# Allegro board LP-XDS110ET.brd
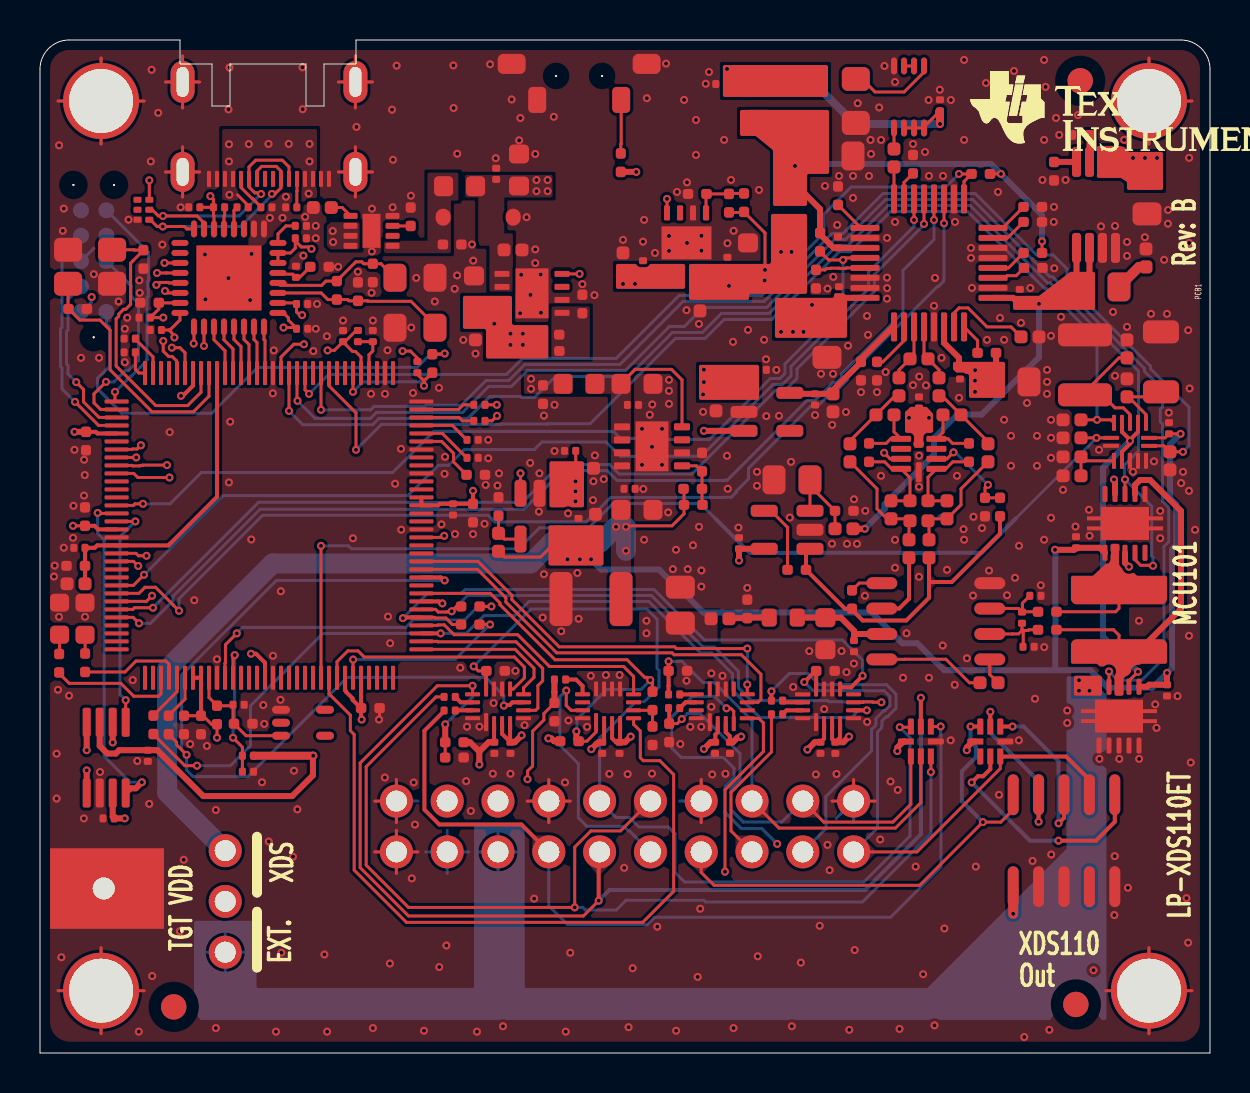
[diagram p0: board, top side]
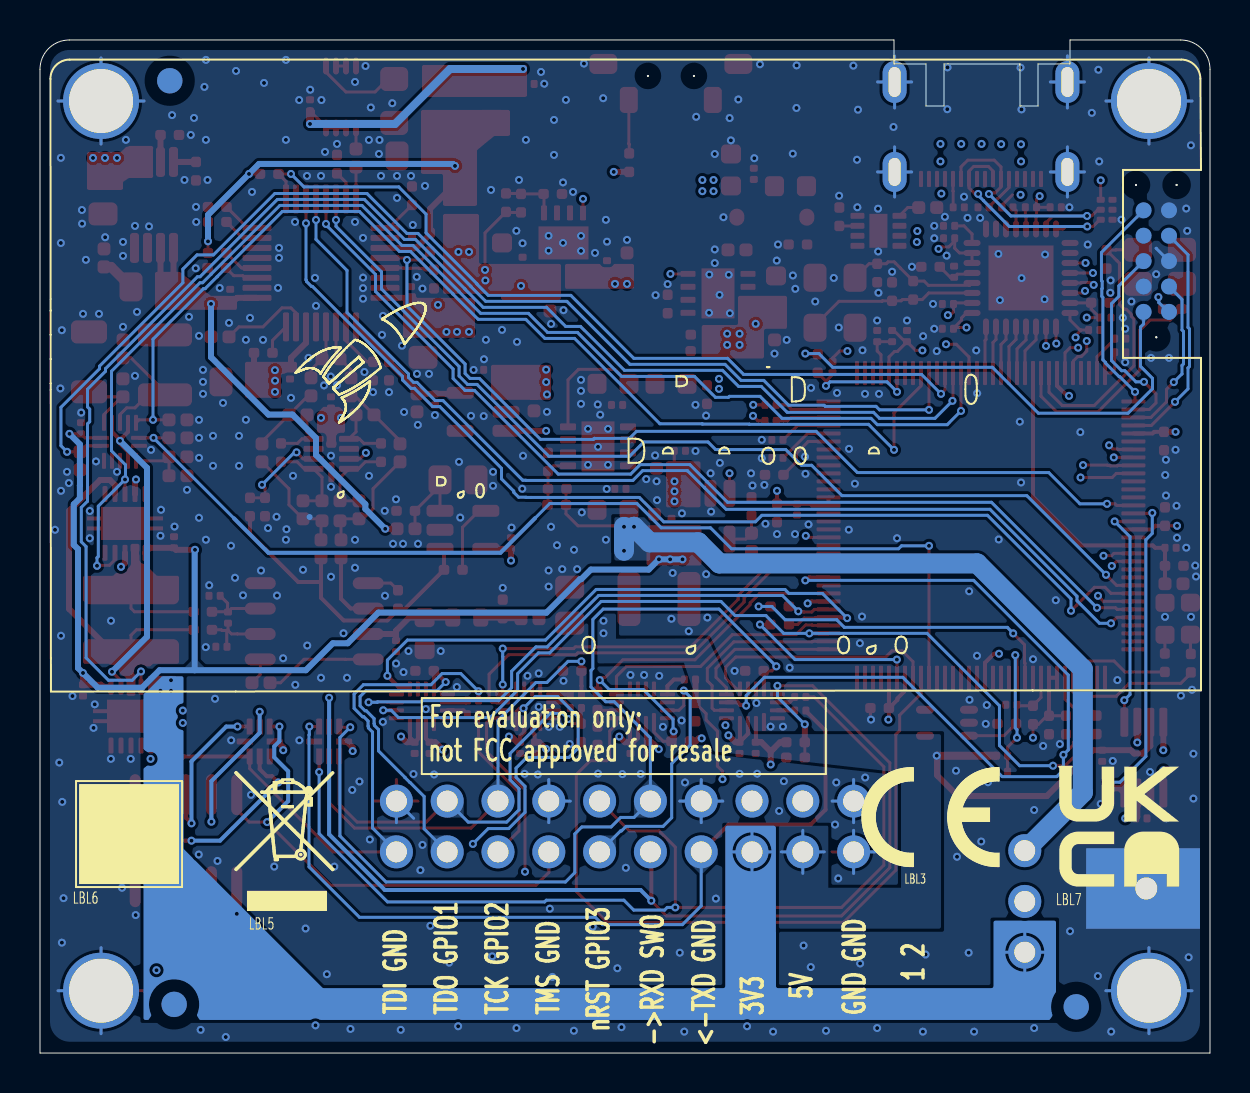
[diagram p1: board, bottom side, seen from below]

Outline 58.5 x 50.67 mm; copper layers: TOP, L2, L3, BOTTOM. Coordinates in mm from the lower left corner of the outline.
Outline path: 0,49.21 0,0 58.5,0 58.5,49.21 arc(58.07,50.24) 57.04,50.67 15.8,50.67 15.8,49.47 14.2,49.47 14.2,47.37 13.3,47.37 13.3,49.47 9.5,49.47 9.5,47.37 8.6,47.37 8.6,49.47 7,49.47 7,50.67 1.46,50.67 arc(0.43,50.24) 0,49.21

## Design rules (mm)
constraint set DEFAULT: min track width 0.15
nets with their own width: min track width 0.15; nets GND

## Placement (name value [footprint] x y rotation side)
C1  12pF  [CAPC1005X60B2N]  5.17 40.16 270 top
C2  10nF  [CAPC1005X60B2N]  16.05 17.25 0 top
C3  10nF  [CAPC1005X60B2N]  2.3 31.07 270 top
C4  10nF  [CAPC1005X60B2N]  2.25 26.37 90 top
C6  100nF  [CAPC0603X35B2N]  6.07 36.16 180 top
C7  10nF  [CAPC1005X60B2N]  7.2 16.87 270 top
C8  100nF  [CAPC0603X35B2N]  9.65 17.42 0 top
C9  12pF  [CAPC1005X60B2N]  1.42 37.22 0 top
C10  100nF  [CAPC0603X35B2N]  5.39 15.15 270 top
C11  100nF  [CAPC0603X35B2N]  3.71 11.74 180 top
C38  100nF  [CAPC0603X35B2N]  20.65 27.47 270 top
C39  100nF  [CAPC0603X35B2N]  15.15 35.58 90 top
C40  1uF  [CAPC1005X60B2N]  21.65 27.47 270 top
C42  1uF  [CAPC1005X60B2N]  8.05 16.87 270 top
C43  100nF  [CAPC0603X35B2N]  2.25 25.27 180 top
C44  1uF  [CAPC1005X60B2N]  2.25 24.37 180 top
C45  2.2uF  [CAPC1005X60A2N]  2.25 23.47 180 top
C46  100nF  [CAPC0603X35B2N]  16.64 35.58 90 top
C47  15pF  [CAPC1005X60B2N]  25.04 35.11 0 top
C48  2.2uF  [CAPC1005X60A2N]  23.2 40.17 0 top
C49  2.2uF  [CAPC1005X60A2N]  22.67 35.67 180 top
C50  10nF  [CAPC1005X60B2N]  9.7 16.47 0 top
C70  100nF  [CAPC0603X35B2N]  22.72 15.55 270 top
C71  100nF  [CAPC0603X35B2N]  23.52 15.55 270 top
C72  100nF  [CAPC0603X35B2N]  28.11 15.55 270 top
C73  100nF  [CAPC0603X35B2N]  28.98 15.55 270 top
C74  100nF  [CAPC0603X35B2N]  39.02 15.55 270 top
C75  100nF  [CAPC0603X35B2N]  39.77 15.55 270 top
C78  100nF  [CAPC0603X35B2N]  12.83 36.23 0 top
C79  100nF  [CAPC0603X35B2N]  7.99 42.3 180 top
C80  100nF  [CAPC0603X35B2N]  12.76 40.75 0 top
C83  100nF  [CAPC0603X35B2N]  5.51 36.78 180 top
C84  100nF  [CAPC0603X35B2N]  12.83 37.47 0 top
C85  4.7uF  [CAPC1005X60B2N]  5.94 37.53 180 top
C86  4.7uF  [CAPC1005X60B2N]  13.51 39.33 0 top
C87  100nF  [CAPC0603X35B2N]  12.8 38.8 90 top
C88  12pF  [CAPC1005X60B2N]  15.9 38.55 270 top
C89  12pF  [CAPC1005X60B2N]  16.64 39.48 270 top
C108  33nF  [CAPC1005X60A2N]  14.56 42.29 180 top
C109  10nF  [CAPC1005X60B2N]  20.15 40.44 0 top
C110  100nF  [CAPC0603X35B2N]  22.81 43.7 90 top
C111  3.3uF  [CAPC1608X100A2N]  23.95 43.37 90 top
C113  22uF  [CAPC1608X100A2N]  21.7 37.27 90 top
C114  100nF  [CAPC0603X35B2N]  56.35 18.42 270 top
C115  100nF  [CAPC0603X35B2N]  34.35 48.47 180 top
C116  100nF  [CAPC0603X35B2N]  39.9 40.27 90 top
C117  10uF  [CAPC2012X150A2N]  38.85 44.87 0 top
C118  100nF  [CAPC0603X35B2N]  45 47.12 90 top
C119  100nF  [CAPC0603X35B2N]  46 34.27 270 top
C120  100nF  [CAPC0603X35B2N]  39.95 37.77 90 top
C121  10uF  [CAPC2012X150A2N]  39.35 36.6 270 top
C122  10uF  [CAPC2012X150A2N]  47.65 33.57 0 top
C123  270pF  [CAPC1005X60B2N]  41.45 29.57 90 top
C124  100nF  [CAPC0603X35B2N]  50.05 22.87 180 top
C125  100nF  [CAPC0603X35B2N]  40.7 20.07 90 top
C126  100nF  [CAPC0603X35B2N]  43.95 32.82 270 top
C127  100nF  [CAPC0603X35B2N]  48.99 37.64 90 top
C128  1uF  [CAPC1005X60B2N]  41.05 34.57 270 top
C129  470pF  [CAPC1005X60A2N]  43.5 26.62 0 top
C130  1nF  [CAPC1005X60A2N]  43.5 27.62 0 top
C131  22nF  [CAPC1005X60A2N]  43.5 34.72 0 top
C132  100nF  [CAPC0603X35B2N]  49.1 22.06 270 top
C133  1uF  [CAPC1005X60B2N]  47.25 27.77 270 top
C134  100nF  [CAPC0603X35B2N]  49.15 20.32 0 top
C135  270pF  [CAPC1005X60B2N]  46.45 29.57 90 top
C136  1uF  [CAPC1005X60B2N]  41.85 34.57 270 top
C137  1uF  [CAPC1005X60B2N]  49.2 39.27 0 top
C138  1uF  [CAPC1005X60B2N]  39.9 42.42 90 top
C139  100nF  [CAPC0603X35B2N]  51.8 25.27 90 top
C140  100nF  [CAPC0603X35B2N]  56.45 30.97 90 top
C141  100nF  [CAPC0603X35B2N]  34.95 25.22 90 top
C142  10uF  [CAPC2012X150A2N]  55.35 43.77 270 top
C143  2.2uF  [CAPC1005X60A2N]  54.35 32.82 90 top
C144  2.2uF  [CAPC1005X60A2N]  54.35 34.77 90 top
C145  1uF  [CAPC1005X60B2N]  50.7 44.57 270 top
C146  47uF  [CAPC2012X150A2N]  52.15 38.32 0 top
C147  10uF  [CAPC2012X150A2N]  38.5 28.67 180 top
C149  2.2uF  [CAPC1005X60A2N]  52.05 29.82 180 top
C151  2.2uF  [CAPC1005X60A2N]  29.15 39.12 90 top
C152  100nF  [CAPC0603X35B2N]  30.15 39.07 90 top
C153  15pF  [CAPC1005X60B2N]  35.2 42.07 90 top
C154  100nF  [CAPC0603X35B2N]  34.37 39.24 90 top
C155  2.2uF  [CAPC1005X60A2N]  33 38.02 270 top
C156  22uF  [CAPC1608X100A2N]  35.4 38.92 90 top
C157  2.2uF  [CAPC1005X60A2N]  33.8 33.02 270 top
C158  100nF  [CAPC0603X35B2N]  38.75 32.97 270 top
C159  2.2uF  [CAPC1005X60A2N]  39.65 32.97 270 top
C160  2.2uF  [CAPC1005X60A2N]  26.77 29.25 0 top
C161  100nF  [CAPC0603X35B2N]  26.79 30.12 180 top
C162  100nF  [CAPC0603X35B2N]  26.92 26.18 90 top
C163  2.2uF  [CAPC1005X60A2N]  27.77 26.05 90 top
C164  100nF  [CAPC0603X35B2N]  35.76 34.17 0 top
C165  22uF  [CAPC1608X100A2N]  39.27 21.77 270 top
C166  10nF  [CAPC1005X60B2N]  35.36 21.75 90 top
C168  10uF  [CAPC2012X150A2N]  32.02 21.5 90 top
C171  22uF  [CAPC1608X100A2N]  29.05 33.47 0 top
C172  15pF  [CAPC1005X60B2N]  32.2 27.42 0 top
C174  22uF  [CAPC1608X100A2N]  29.05 27.17 0 top
C175  100nF  [CAPC0603X35B2N]  29.37 32.42 0 top
C484  10nF  [CAPC1005X60B2N]  25.15 33.39 270 top
C485  100nF  [CAPC0603X35B2N]  29.2 28.22 0 top
C486  220uF  [CAPC3225X280A2N]  29.05 22.71 180 top
C487  100nF  [CAPC0603X35B2N]  34.5 15.55 270 top
C488  100nF  [CAPC0603X35B2N]  33.75 15.55 270 top
CR4  LS_Q976-NR-1  [LEDC1608X80B2N]  0.98 22.52 270 top
CR5  LG_Q396-PS-35  [LEDC1608X40N]  2.25 22.52 270 top
CR6  TPD4E004DRY  [SON50P100X145X60-6N]  4.88 42.68 270 top
CR7  TPD6E004RSER  [QFN50P150X150X60-8N]  47.02 14.83 0 top
CR15  MBR130T1  [SOD3716X135N]  20.16 41.81 0 top
CR16  TPD6E004RSER  [QFN50P150X150X60-8N]  43.54 14.83 0 top
FIDU1  FIDU_1.27mm  [FID127X142]  52.01 48.63 0 top
FIDU2  FIDU_1.27mm  [FID127X142]  6.69 2.31 0 top
FIDU3  FIDU_1.27mm  [FID127X142]  51.79 2.43 0 top
FIDU4  FIDU_1.27mm  [FID127X142]  52.01 48.63 180 bottom
FIDU5  FIDU_1.27mm  [FID127X142]  6.69 2.31 180 bottom
FIDU6  FIDU_1.27mm  [FID127X142]  51.79 2.43 180 bottom
FL2  BLM18HE152SN1  [FIL_BLM18HE152SN1DN#2]  21.78 43.36 180 top
FL4  BLM18HE152SN1  [FIL_BLM18HE152SN1DN]  37.86 21.78 180 top
FL5  BLM18HE152SN1  [FIL_BLM18HE152SN1DN#2]  27.75 33.47 180 top
J1  U20405-2  [MUP_U204052_A2N]  14.45 43.72 90 top
L332  BLM21PG221SN1  [FILC2012X110A2N]  35.92 46.6 90 top
L333  BLM21PG221SN1  [FILC2012X110A2N]  37.5 41.32 90 top
L334  BLM21PG221SN1  [FILC2012X110A2N]  37.5 37.02 90 top
LBL2  TI_LOGO  [TI_LOGO_1]  47.5 49.12 0 top
LBL3  CE_label  [CE_MARKING]  14.81 9.3 180 bottom
LBL4  -  [LABEL_FOR_EVALUATION_ONLY]  39.26 14.1 180 bottom
LBL5  TRASH_7mm  [TRASH_7MM]  48.15 7.11 180 bottom
LBL6  ESD_LABEL_5x5mm  [ESD_LABEL_5X5]  56.55 8.45 180 bottom
LBL7  LABEL_UKCA_6x6mm  [LABEL_UKCA_6MM]  7.54 8.32 180 bottom
M1  SNT-100-BK-G  [SAMTEC_SNT100BKG]  7.99 11.42 270 top
M15  DCB-10  [MECH_DCB10_A2B]  3.05 47.62 180 bottom
M16  DCB-10  [MECH_DCB10_A2B]  55.45 47.62 180 bottom
M17  DCB-10  [MECH_DCB10_A2B]  3.05 3.12 180 bottom
M18  DCB-10  [MECH_DCB10_A2B]  55.45 3.12 180 bottom
MH1  HOLE_3.2mm_PTH  [MTG320_380]  3.05 3.12 0 top
MH2  HOLE_3.2mm_PTH  [MTG320_380]  55.45 3.12 0 top
MH3  HOLE_3.2mm_PTH  [MTG320_380]  3.05 47.62 0 top
MH4  HOLE_3.2mm_PTH  [MTG320_380]  55.45 47.62 0 top
MH5  HOLE_1.1mm_PTH  [MTG110_170]  3.19 8.23 0 top
NOREF  -  []  0.85 -97.91 0 top
NOREF#2  -  []  -45.65 -121.98 0 top
NOREF#3  -  []  51.48 20.39 180 bottom
P7  FTSH-105-01-F-DV-K  [SAMTEC_FTSH-105-01-F-DV-K-10L]  48.66 8.32 0 top
P8  TC2050-IDC-NL  [TAGCONNECT_TC2050IDCNL_A2N]  2.05 37.07 90 bottom
P9  BB02-HC031-KB1-603000  [GRADCONN_BB02HC031KB1603000_A2B]  9.26 10.12 270 top
P10  CNT-B254-210-GD-910/3.2  [CNT_CNTB254210GD91032_A2B]  17.82 10.06 0 top
PCB1  MCU101  [TI_MCUXX]  57.45 37.77 90 top
R8  51  [RESC0603X35B2N]  25.72 18.68 0 top
R9  51  [RESC0603X35B2N]  36.57 17.63 0 top
R10  100k  [RESC1005X40B2N]  32.35 19.11 180 top
R11  100k  [RESC1005X40B2N]  31.46 15.55 90 top
R12  51  [RESC0603X35B2N]  31.43 17.25 0 top
R13  51  [RESC0603X35B2N]  31.43 17.94 0 top
R14  51  [RESC0603X35B2N]  20.2 17.13 0 top
R15  51  [RESC0603X35B2N]  20.2 17.81 0 top
R16  51  [RESC0603X35B2N]  36.57 16.94 0 top
R17  10k  [RESC0603X35B2N]  18.87 34.03 90 top
R18  4.7k  [RESC1005X40B2N]  8.85 17.37 270 top
R20  100  [RESC1005X40B2N]  19.62 34.03 90 top
R23  180  [RESC1005X40B2N]  0.96 19.96 270 top
R25  220  [RESC1005X40B2N]  2.26 19.98 270 top
R27  1k  [RESC0603X35B2N]  22.25 31.62 180 top
R28  4.87k  [RESC1005X40B2N]  22.25 28.92 180 top
R29  1k  [RESC0603X35B2N]  21.35 30.67 0 top
R30  1k  [RESC0603X35B2N]  21.35 29.77 0 top
R31  51  [RESC0603X35B2N]  15.9 35.58 90 top
R33  51k  [RESC1005X40B2N]  25.96 35.93 180 top
R34  30k  [RESC1005X40B2N]  27.12 37.93 270 top
R39  1k  [RESC0603X35B2N]  22.25 32.42 180 top
R57  100  [RESC1005X40B2N]  29.04 44.07 90 top
R58  3.3k  [RESC1005X40B2N]  26.93 15.6 180 top
R61  100k  [RESC1005X40B2N]  20.26 15.54 0 top
R62  100k  [RESC1005X40B2N]  23.24 19.11 180 top
R63  100k  [RESC1005X40B2N]  39.73 19.11 180 top
R65  100k  [RESC1005X40B2N]  25.72 16.59 90 top
R82  10k  [RESC0603X35B2N]  9.85 42.3 0 top
R83  10k  [RESC0603X35B2N]  8.67 42.3 0 top
R84  12k  [RESC0603X35B2N]  13.32 41.37 180 top
R87  1Meg  [RESC1005X40B2N]  14.84 37.69 90 top
R90  1k  [RESC0603X35B2N]  4.21 35.73 0 top
R91  1k  [RESC0603X35B2N]  4.21 35.05 0 top
R92  10k  [RESC0603X35B2N]  10.12 14.87 0 top
R93  20k  [RESC0603X35B2N]  10.12 14.07 0 top
R94  22  [RESC1005X40A2N]  42.7 44.32 90 top
R95  1.2k  [RESC1005X40A2N]  40.5 30.47 270 top
R96  100k  [RESC1005X40B2N]  47.5 43.97 180 top
R97  100k  [RESC1005X40B2N]  38.8 39.17 270 top
R98  100k  [RESC1005X40B2N]  47.8 35.02 180 top
R99  0  [RESC1005X40B2N]  49.9 22.07 0 top
R100  0  [RESC1005X40B2N]  40.6 22.22 90 top
R101  1.2k  [RESC1005X40A2N]  43.45 25.67 270 top
R102  330  [RESC1005X40A2N]  42.55 27.62 270 top
R103  4.99  [RESC1005X40A2N]  41.8 31.92 0 top
R104  10  [RESC1005X40A2N]  42.95 33.77 270 top
R105  100k  [RESC1005X40B2N]  43.65 44.92 270 top
R107  1  [RESC3246X70A2N]  53.95 20.12 90 top
R108  0  [RESC1005X40B2N]  49.9 21.17 0 top
R109  1.2k  [RESC1005X40A2N]  44.45 25.67 270 top
R110  330  [RESC1005X40A2N]  45.35 27.62 270 top
R111  0  [RESC1005X40B2N]  48 27.77 270 top
R112  4.99  [RESC1005X40A2N]  46.05 31.92 180 top
R113  10  [RESC1005X40A2N]  44.95 33.77 270 top
R114  100k  [RESC1005X40B2N]  39 41.02 270 top
R116  60.4k  [RESC1005X40A2N]  49.95 35.82 180 top
R117  100k  [RESC1005X40B2N]  50.1 42.32 180 top
R118  100k  [RESC1005X40B2N]  50.1 41.57 180 top
R119  100k  [RESC1005X40B2N]  50.1 40.02 180 top
R120  1.2k  [RESC1005X40A2N]  47.4 30.47 270 top
R121  22k  [RESC1005X40A2N]  40.65 26.22 180 top
R122  0.22  [RESC1005X50A2N]  55.3 40.22 270 top
R123  82  [RESC3216X75A2N]  56.05 36.07 270 top
R125  36.5  [RESC3225X75A2N]  52.25 35.92 270 top
R126  4.7k  [RESC1005X40B2N]  39.75 27.12 0 top
R127  47k  [RESC1005X40A2N]  52.05 30.77 180 top
R128  47k  [RESC1005X40A2N]  52.05 31.67 180 top
R129  47k  [RESC1005X40A2N]  56.5 30.07 270 top
R130  2.2k  [RESC1005X40A2N]  52.05 28.87 180 top
R131  0  [RESC1005X40B2N]  38.3 24.17 180 top
R132  51k  [RESC1005X40B2N]  34.45 42.97 270 top
R133  30k  [RESC1005X40B2N]  32.4 42.97 0 top
R134  60.4k  [RESC1005X40A2N]  22.92 26 270 top
R135  30k  [RESC1005X40B2N]  22.92 27.8 270 top
R136  100k  [RESC1005X40B2N]  51.55 45.92 0 top
R137  2.61k  [RESC1005X40A2N]  47 18.52 0 top
R151  51k  [RESC1005X40B2N]  33.1 28.22 180 top
R152  30k  [RESC1005X40B2N]  33.1 30.02 270 top
R353  4.7k  [RESC1005X40B2N]  18.53 42.29 270 top
R354  10  [RESC1005X40A2N]  34.45 21.72 180 top
R357  5.1k  [RESC0603X35B2N]  12.28 42.3 0 top
R358  5.1k  [RESC0603X35B2N]  11.6 42.3 180 top
R359  100k  [RESC1005X40B2N]  21.18 14.78 180 top
R360  0  [RESC1005X40B2N]  6.44 16.87 270 top
R361  0  [RESC1005X40B2N]  21.98 22.34 180 top
R362  0  [RESC1005X40B2N]  21.97 21.43 180 top
R363  0  [RESC1005X40B2N]  30.63 18.07 270 top
R364  0  [RESC1005X40B2N]  30.63 16.33 270 top
R365  0  [RESC1005X40B2N]  5.67 16.88 270 top
SW3  1188E-1K2  [SW_1188E1K2V_A2N]  30.33 49.47 180 top
U5  MSP432E401YTPDT  [QFP40P1600X1600X120-128A2N]  5.25 18.77 0 top
U6  LM4040B25IDCK  [SOT65P210X110-5N]  12.05 17.17 270 top
U7  TPS79601DR  [SON65P300X300X100-9AN]  23.1 38.97 270 top
U8  SN74AVC4T245RSV  [QFNFC40P180X260X55-16A2N]  22.3 16.55 0 top
U9  SN74AVC4T245RSV  [QFNFC40P180X260X55-16A2N]  38.8 16.55 0 top
U10  SN74AVC4T245RSV  [QFNFC40P180X260X55-16A2N]  27.8 16.55 0 top
U15  USB3300-EZK  [QFNWB50P500X500X100-33N]  11.2 41.22 180 top
U33  TS3A24159DRC  [SON50P300X300X100-11A2N]  53.25 25.02 0 top
U34  SN74LVC2G74DCU  [SOP50P310X90-8N]  44.2 49.37 180 top
U35  ADS127L01IPBS  [QFP50P700X700X120-32A2N]  42.7 36.32 0 top
U36  INA118UB  [SOIC127P600X175-8N]  47.49 19.69 90 top
U37  THS4551IRUN  [QFNFCP50P200X200X80-10A2N]  43.05 30.72 270 top
U38  TS3A24159DRC  [SON50P300X300X100-11A2N]  54.95 18.32 180 top
U39  TS3A4751RUCR  [QFNFC40P200X200X40-14A2N]  55.3 31.52 180 top
U40  REF6025IDGK  [SOP65P490X110-8A2N]  53.77 44.57 180 top
U41  OPA320AIDBV  [SOT95P280X145-5A2N]  38.5 25.22 90 top
U42  TPS79601DR  [SON65P300X300X100-9AN]  31.35 39.02 0 top
U43  LP5907MFX-1.8  [SOT95P280X145-5A2N]  35.2 33.02 270 top
U44  TPS73101DBV  [SOT95P280X145-5A2N]  25.92 28 180 top
U46  TPS79601DR  [SON65P300X300X100-9AN]  29.1 31.32 270 top
U47  TPS259530DSG  [SON50P200X200X80-9A2N]  15.53 41.87 270 top
U49  SN74AVC4T245RSV  [QFNFC40P180X260X55-16A2N]  33.49 16.55 0 top
U50  TCA9406DCT  [SOP65P400X130-8A2N]  2.33 13 0 top
Y3  16MHz  [OSCCC250X320X100-4BN]  1.4 38.48 0 top
Y4  24MHz  [OSCCC250X320X70-4AN]  17.75 38.78 270 top
Y5  16.384MHz  [OSCSC254P320X500X130-4A2N]  38.25 46.52 0 top

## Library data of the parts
C1-C4 C7 C9 C40 C42 C44 C47 C50 C85 C86 C88 C89 C109 C123 C128 C133 C135-C138 C145 C153 C166 C172 C484 = CAPACITOR: User Part Number: #PN
C6 C8 C10 C11 C38 C39 C43 C46 C70-C75 C78-C80 C83 C84 C87 C110 C114-C116 C118-C120 C124-C127 C132 C134 C139-C141 C152 C154 C158 C161 C162 C164 C175 C485 C487 C488 = CAPACITOR: User Part Number: #PN; alternate symbols: (CAPC0603X35B2L,CAPC0603X35B2M)
C45 C48 C49 C108 C129-C131 C143 C144 C149 C151 C155 C157 C159 C160 C163 = CAPACITOR: User Part Number: #PN; alternate symbols: (CAPC1005X60A2L,CAPC1005X60A2M)
C111 C113 C156 C165 C171 C174 = CAPACITOR: User Part Number: #PN; alternate symbols: (CAPC1608X100A2L,CAPC1608X100A2M)
C117 C121 C122 C142 C146 C147 C168 = CAPACITOR: User Part Number: #PN; alternate symbols: (CAPC2012X150A2L,CAPC2012X150A2M)
C486 = CAPACITOR: User Part Number: #PN; alternate symbols: (CAPC3225X280A2L,CAPC3225X280A2M)
CR4 = LED: User Part Number: #PN; alternate symbols: (LEDC1608X80B2L,LEDC1608X80B2M)
CR5 = LED: alternate symbols: (LEDC1608X40L,LEDC1608X40M)
CR6 = DIODE_TPD4E004_SON6: User Part Number: #PN; alternate symbols: (SON50P100X145X65-6L,SON50P100X145X65-6M)
CR7 CR16 = DIODE_TVS_TPD6E004_QFN8_V1: User Part Number: #PN; alternate symbols: (QFN50P150X150X60-8L,QFN50P150X150X60-8M)
CR15 = DIODE_SCHOTTKY: alternate symbols: (SOD3716X135L,SOD3716X135M,SOD3716X135BN)
FIDU1-FIDU6 = FIDMARK
FL2 FL4 FL5 = FILTER_2PIN: alternate symbols: (FIL_BLM18HE152SN1DL,FIL_BLM18HE152SN1DM)
J1 = CONN_USB_TYPE-C_16PINS: User Part Number: #PN; alternate symbols: (MUP_U204052_A2L,MUP_U204052_A2M)
L332-L334 = INDUCTOR: User Part Number: #PN; alternate symbols: (FILC2012X110A2L,FILC2012X110A2M)
LBL2 = TI_LOGO_V1
LBL3 = CE_LABEL_V1
LBL4 = LABEL_FOR_EVALUATOIN_ONLY: User Part Number: #PN
LBL5 = TRASH_V2: User Part Number: #PN
LBL6 = ESD_LABEL: User Part Number: #PN
LBL7 = LABEL_UKCA: User Part Number: #PN
M1 = MECH_SHUNT_JUMPER_V1: User Part Number: #PN
M15-M18 = MECH_SPACERS_SUPPORT_V1: User Part Number: #PN
MH1-MH5 = HOLE_PTH
P7 = CONN_HEADER_2X5: alternate symbols: (SAMTEC_FTSH10501FDVK_A2L,SAMTEC_FTSH10501FDVK_A2M)
P8 = CONN_IDC_TC2050-IDC-NL: User Part Number: #PN; alternate symbols: (TAGCONNECT_TC2050IDCNL_A2L,TAGCONNECT_TC2050IDCNL_A2M)
P9 = CONN_HEADER_3_P_S: User Part Number: #PN; alternate symbols: (GRADCONN_BB02HC031KB1603000_A2C,GRADCONN_BB02HC031KB1603000_A2A)
P10 = CONN_HEADER_2X10_P_V3: User Part Number: #PN; alternate symbols: (CNT_CNTB254210GD91032_A2A,CNT_CNTB254210GD91032_A2C)
PCB1 = PCB_V2: User Part Number: #PN
R8 R9 R12-R17 R27 R29-R31 R39 R82-R84 R90-R93 R357 R358 = RESISTOR: User Part Number: #PN; alternate symbols: (RESC0603X35B2L,RESC0603X35B2M)
R10 R11 R18 R20 R23 R25 R28 R33 R34 R57 R58 R61-R63 R65 R87 R96-R100 R105 R108 R111 R114 R117-R119 R126 R131-R133 R135 R136 R151 R152 R353 R359-R365 = RESISTOR: User Part Number: #PN
R94 R95 R101-R104 R109 R110 R112 R113 R116 R120 R121 R127-R130 R134 R137 R354 = RESISTOR: User Part Number: #PN; alternate symbols: (RESC1005X40A2L,RESC1005X40A2M)
R107 = RESISTOR: User Part Number: #PN; alternate symbols: (RESC3246X70A2L,RESC3246X70A2M)
R122 = RESISTOR: User Part Number: #PN; alternate symbols: (RESC1005X50A2L,RESC1005X50A2M)
R123 = RESISTOR: User Part Number: #PN; alternate symbols: (RESC3216X75A2L,RESC3216X75A2M)
R125 = RESISTOR: User Part Number: #PN; alternate symbols: (RESC3225X75A2L,RESC3225X75A2M)
SW3 = SWITCH_TACT_V2: alternate symbols: (SW_1188E1K2V_A2L,SW_1188E1K2V_A2M)
U5 = IC_PROC_MSP432E401Y_TQFP128: User Part Number: #PN; alternate symbols: (QFP40P1600X1600X120-128A2L,QFP40P1600X1600X120-128A2M)
U6 = IC_REF_LM4040_SC70-5: alternate symbols: (SOT65P210X110-5L,SOT65P210X110-5M)
U7 U42 U46 = IC_PM_TPS79601_SON8: alternate symbols: (SON65P300X300X100-9AL,SON65P300X300X100-9AM)
U8-U10 U49 = IC_XCVR_SN74AVC4T245_UQFN16_2: User Part Number: #PN; alternate symbols: (QFNFC40P180X260X55-16A2L,QFNFC40P180X260X55-16A2M)
U15 = IC_PROC_USB3300_QFN32: alternate symbols: (QFNWB50P500X500X100-33L,QFNWB50P500X500X100-33M,QFNWB50P500X500X100-33DL,QFNWB50P500X500X100-33DM)
U33 U38 = IC_SWITCH_TS3A24159_SON10: User Part Number: #PN; alternate symbols: (SON50P300X300X100-11A2L,SON50P300X300X100-11A2M)
U34 = IC_LOGIC_SN74LVC2G74_VSSOP8: alternate symbols: (SOP50P310X90-8L,SOP50P310X90-8M)
U35 = IC_ADC_ADS127L01_QFP32_0: User Part Number: #PN; alternate symbols: (QFP50P700X700X120-32A2L,QFP50P700X700X120-32A2M)
U36 = IC_OPAMP_INA118U_SO8: alternate symbols: (SOIC127P600X175-8A2L,SOIC127P600X175-8A2M)
U37 = IC_OPAMP_THS4551_QFN10: User Part Number: #PN; alternate symbols: (QFNFCP50P200X200X80-10A2L,QFNFCP50P200X200X80-10A2M)
U39 = IC_SWITCH_TS3A4751_QFN14: User Part Number: #PN; alternate symbols: (QFNFC40P200X200X40-14A2L,QFNFC40P200X200X40-14A2M)
U40 = IC_REF_REF6025_VSSOP8: User Part Number: #PN; alternate symbols: (SOP65P490X110-8A2L,SOP65P490X110-8A2M)
U41 = IC_OPAMP_OPA320_SOT23-5: User Part Number: #PN; alternate symbols: (SOT95P280X145-5A2L,SOT95P280X145-5A2M)
U43 = IC_PM_LP5907-1_8_SOT23-5: User Part Number: #PN; alternate symbols: (SOT95P280X145-5A2L,SOT95P280X145-5A2M)
U44 = IC_PM_TPS73101_SOT23-5: User Part Number: #PN; alternate symbols: (SOT95P280X145-5A2L,SOT95P280X145-5A2M)
U47 = IC_PM_TPS259530_WSON8: alternate symbols: (SON50P200X200X80-9A2L,SON50P200X200X80-9A2M)
U50 = IC_PERIPH_TCA9406_SM8: User Part Number: #PN; alternate symbols: (SOP65P400X130-8A2L,SOP65P400X130-8A2M)
Y3 = XTAL_4: alternate symbols: (OSCCC250X320X100-4BL,OSCCC250X320X100-4BM)
Y4 = XTAL_4: alternate symbols: (OSCCC250X320X70-4AL,OSCCC250X320X70-4AM)
Y5 = XTAL_GEN_EN_V1: User Part Number: #PN; alternate symbols: (OSCSC254P320X500X130-4A2L,OSCSC254P320X500X130-4A2M)

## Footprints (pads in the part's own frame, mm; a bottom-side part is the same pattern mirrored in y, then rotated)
CAPC0603X35B2N
  custom 0.087x0.087 smd: 1(0,0) 2(0.56,0)
CAPC1005X60A2N
  custom 0.16x0.16 smd: 1(0,0) 2(0.9,0)
CAPC1005X60B2N
  custom 0.125x0.125 smd: 1(0,0) 2(0.924,0)
CAPC1608X100A2N
  custom 0.237x0.237 smd: 1(0,0) 2(1.6,0)
CAPC2012X150A2N
  custom 0.287x0.287 smd: 1(0,0) 2(1.8,0)
CAPC3225X280A2N
  custom 0.287x0.287 smd: 1(0,0) 2(3,0)
CNT_CNTB254210GD91032_A2B
  round 1.65 hole 1.05: 1(0,0) 2(0,2.54) 3(2.54,0) 4(2.54,2.54) 5(5.08,0) 6(5.08,2.54) 7(7.62,0) 8(7.62,2.54) 9(10.16,0) 10(10.16,2.54) 11(12.7,0) 12(12.7,2.54) 13(15.24,0) 14(15.24,2.54) 15(17.78,0) 16(17.78,2.54) 17(20.32,0) 18(20.32,2.54) 19(22.86,0) 20(22.86,2.54)
FID127X142
  round 1.27 smd: 1(0,0)
FIL_BLM18HE152SN1DN
  custom 0.188x0.188 smd: 1(0,0) 2(1.4,0)
FIL_BLM18HE152SN1DN#2
  custom 0.237x0.237 smd: 1(0,0) 2(1.6,0)
FILC2012X110A2N
  custom 0.287x0.287 smd: 1(0,0) 2(1.8,0)
GRADCONN_BB02HC031KB1603000_A2B
  round 1.65 hole 1.05: 1(0,0) 2(2.54,0) 3(5.08,0)
LEDC1608X40N
  custom 0.225x0.225 smd: 1(0,0) 2(1.6,0)
LEDC1608X80B2N
  custom 0.225x0.225 smd: 1(0,0) 2(1.6,0)
MTG110_170
  round 1.699 hole 1.1: 1(0,0)
MTG320_380
  round 3.8 hole 3.2: 1(0,0)
MUP_U204052_A2N
  custom 0.05x0.05 smd: C1(0,0) C2(0,0.4) C3(0,0.8) C4(0,1.2) C5(0,1.6) C6(0,2) C7(0,2.4) C8(0,2.8) C9(0,3.2) C10(0,3.6) C11(0,4) C12(0,4.4) C13(0,4.8) C14(0,5.2) C15(0,5.6) C16(0,6)
  oval 2x1.2 hole 1.4x0.6: M1(0.35,-1.32) M4(0.35,7.32)
  oval 2.1x1.2 hole 1.5x0.6: M2(4.85,-1.32) M3(4.85,7.32)
OSCCC250X320X70-4AN
  custom 0.287x0.287 smd: 1(0,0) 2(2.5,0) 3(2.5,2) 4(0,2)
OSCCC250X320X100-4BN
  custom 0.299x0.299 smd: 1(0,0) 2(2.2,0) 3(2.2,1.7) 4(0,1.7)
OSCSC254P320X500X130-4A2N
  custom 0.3x0.3 smd: 1(0,0) 2(2.54,0) 3(2.54,2.2) 4(0,2.2)
QFN50P150X150X60-8N
  custom 0.075x0.075 smd: 1(0,0) 2(0.5,0) 3(1,0) 4(1.25,0.75) 5(1,1.5) 6(0.5,1.5) 7(0,1.5) 8(-0.25,0.75)
QFNFC40P180X260X55-16A2N
  custom 0.05x0.05 smd: 1(0,0) 2(0.4,-0.075) 3(0.8,-0.075) 4(1.2,-0.075) 5(1.875,0.19) 6(1.875,0.59) 7(1.875,0.99) 8(1.875,1.39) 9(1.2,1.655) 10(0.8,1.655) 11(0.4,1.655) 12(0,1.655) 13(-0.675,1.39) 14(-0.675,0.99) 15(-0.675,0.59) 16(-0.675,0.19)
QFNFC40P200X200X40-14A2N
  custom 0.05x0.05 smd: 1(0,0) 2(0.4,0) 3(0.8,0) 4(1.2,0) 5(1.6,0) 6(1.75,0.75) 7(1.75,1.15) 8(1.6,1.9) 9(1.2,1.9) 10(0.8,1.9) 11(0.4,1.9) 12(0,1.9) 13(-0.15,1.15) 14(-0.15,0.75)
QFNFCP50P200X200X80-10A2N
  custom 0.075x0.075 smd: 1(0,0) 2(0.5,0) 3(1,0) 4(1.5,0) 5(1.67,0.885) 6(1.5,1.77) 7(1,1.77) 8(0.5,1.77) 9(0,1.77) 10(-0.1,0.885)
QFNWB50P500X500X100-33N
  oval 0.3x0.851 smd: 1(0,0) 2(0.5,0) 3(1,0) 4(1.5,0) 5(2,0) 6(2.5,0) 7(3,0) 8(3.5,0) 17(3.5,4.9) 18(3,4.9) 19(2.5,4.9) 20(2,4.9) 21(1.5,4.9) 22(1,4.9) 23(0.5,4.9) 24(0,4.9)
  oval 0.851x0.3 smd: 9(4.2,0.7) 10(4.2,1.2) 11(4.2,1.7) 12(4.2,2.2) 13(4.2,2.7) 14(4.2,3.2) 15(4.2,3.7) 16(4.2,4.2) 25(-0.7,4.2) 26(-0.7,3.7) 27(-0.7,3.2) 28(-0.7,2.7) 29(-0.7,2.2) 30(-0.7,1.7) 31(-0.7,1.2) 32(-0.7,0.7)
  rect 3.25x3.25 smd: 33(1.75,2.45)
QFP40P1600X1600X120-128A2N
  custom 0.05x0.05 smd: 1(0,0) 2(0.4,0) 3(0.8,0) 4(1.2,0) 5(1.6,0) 6(2,0) 7(2.4,0) 8(2.8,0) 9(3.2,0) 10(3.6,0) 11(4,0) 12(4.4,0) 13(4.8,0) 14(5.2,0) 15(5.6,0) 16(6,0) 17(6.4,0) 18(6.8,0) 19(7.2,0) 20(7.6,0) 21(8,0) 22(8.4,0) 23(8.8,0) 24(9.2,0) 25(9.6,0) 26(10,0) 27(10.4,0) 28(10.8,0) 29(11.2,0) 30(11.6,0) 31(12,0) 32(12.4,0) 33(13.82,1.42) 34(13.82,1.82) 35(13.82,2.22) 36(13.82,2.62) 37(13.82,3.02) 38(13.82,3.42) 39(13.82,3.82) 40(13.82,4.22) 41(13.82,4.62) 42(13.82,5.02) 43(13.82,5.42) 44(13.82,5.82) 45(13.82,6.22) 46(13.82,6.62) 47(13.82,7.02) 48(13.82,7.42) 49(13.82,7.82) 50(13.82,8.22) 51(13.82,8.62) 52(13.82,9.02) 53(13.82,9.42) 54(13.82,9.82) 55(13.82,10.22) 56(13.82,10.62) 57(13.82,11.02) 58(13.82,11.42) 59(13.82,11.82) 60(13.82,12.22) 61(13.82,12.62) 62(13.82,13.02) 63(13.82,13.42) 64(13.82,13.82) 65(12.4,15.24) 66(12,15.24) 67(11.6,15.24) 68(11.2,15.24) 69(10.8,15.24) 70(10.4,15.24) 71(10,15.24) 72(9.6,15.24) 73(9.2,15.24) 74(8.8,15.24) 75(8.4,15.24) 76(8,15.24) 77(7.6,15.24) 78(7.2,15.24) 79(6.8,15.24) 80(6.4,15.24) 81(6,15.24) 82(5.6,15.24) 83(5.2,15.24) 84(4.8,15.24) 85(4.4,15.24) 86(4,15.24) 87(3.6,15.24) 88(3.2,15.24) 89(2.8,15.24) 90(2.4,15.24) 91(2,15.24) 92(1.6,15.24) 93(1.2,15.24) 94(0.8,15.24) 95(0.4,15.24) 96(0,15.24) 97(-1.42,13.82) 98(-1.42,13.42) 99(-1.42,13.02) 100(-1.42,12.62) 101(-1.42,12.22) 102(-1.42,11.82) 103(-1.42,11.42) 104(-1.42,11.02) 105(-1.42,10.62) 106(-1.42,10.22) 107(-1.42,9.82) 108(-1.42,9.42) 109(-1.42,9.02) 110(-1.42,8.62) 111(-1.42,8.22) 112(-1.42,7.82) 113(-1.42,7.42) 114(-1.42,7.02) 115(-1.42,6.62) 116(-1.42,6.22) 117(-1.42,5.82) 118(-1.42,5.42) 119(-1.42,5.02) 120(-1.42,4.62) 121(-1.42,4.22) 122(-1.42,3.82) 123(-1.42,3.42) 124(-1.42,3.02) 125(-1.42,2.62) 126(-1.42,2.22) 127(-1.42,1.82) 128(-1.42,1.42)
QFP50P700X700X120-32A2N
  custom 0.075x0.075 smd: 1(0,0) 2(0.5,0) 3(1,0) 4(1.5,0) 5(2,0) 6(2.5,0) 7(3,0) 8(3.5,0) 9(4.95,1.45) 10(4.95,1.95) 11(4.95,2.45) 12(4.95,2.95) 13(4.95,3.45) 14(4.95,3.95) 15(4.95,4.45) 16(4.95,4.95) 17(3.5,6.4) 18(3,6.4) 19(2.5,6.4) 20(2,6.4) 21(1.5,6.4) 22(1,6.4) 23(0.5,6.4) 24(0,6.4) 25(-1.45,4.95) 26(-1.45,4.45) 27(-1.45,3.95) 28(-1.45,3.45) 29(-1.45,2.95) 30(-1.45,2.45) 31(-1.45,1.95) 32(-1.45,1.45)
RESC0603X35B2N
  custom 0.087x0.087 smd: 1(0,0) 2(0.56,0)
RESC1005X40A2N
  custom 0.16x0.16 smd: 1(0,0) 2(0.9,0)
RESC1005X40B2N
  custom 0.125x0.125 smd: 1(0,0) 2(0.924,0)
RESC1005X50A2N
  custom 0.16x0.16 smd: 1(0,0) 2(0.9,0)
RESC3216X75A2N
  custom 0.287x0.287 smd: 1(0,0) 2(3,0)
RESC3225X75A2N
  custom 0.287x0.287 smd: 1(0,0) 2(3,0)
RESC3246X70A2N
  custom 0.287x0.287 smd: 1(0,0) 2(2.9,0)
SAMTEC_FTSH-105-01-F-DV-K-10L
  oval 0.551x2.05 smd: 1(0,0) 2(0,4.6) 3(1.27,0) 4(1.27,4.6) 5(2.54,0) 6(2.54,4.6) 7(3.81,0) 8(3.81,4.6) 9(5.08,0) 10(5.08,4.6)
SOD3716X135N
  oval 0.75x0.85 smd: 1(0,0) 2(3.5,0)
SOIC127P600X175-8N
  oval 0.6x1.55 smd: 1(0,0) 2(1.27,0) 3(2.54,0) 4(3.81,0) 5(3.81,5.4) 6(2.54,5.4) 7(1.27,5.4) 8(0,5.4)
SON50P100X145X60-6N
  custom 0.075x0.075 smd: 1(0,0) 2(0.5,0) 3(1,0) 4(1,0.59) 5(0.5,0.59) 6(0,0.59)
SON50P200X200X80-9A2N
  custom 0.075x0.075 smd: 1(0,0) 2(0.5,0) 3(1,0) 4(1.5,0) 5(1.5,2.1) 6(1,2.1) 7(0.5,2.1) 8(0,2.1)
  rect 1.7x0.9 smd: 9(0.75,1.05)
SON50P300X300X100-11A2N
  custom 0.062x0.062 smd: 1(0,0) 2(0.5,0) 3(1,0) 4(1.5,0) 5(2,0) 6(2,2.94) 7(1.5,2.94) 8(1,2.94) 9(0.5,2.94) 10(0,2.94)
  custom 0.412x0.412 smd: 11(1,1.47)
SON65P300X300X100-9AN
  custom 0.087x0.087 smd: 1(0,0) 2(0.65,0) 3(1.3,0) 4(1.95,0) 5(1.95,3) 6(1.3,3) 7(0.65,3) 8(0,3)
  rect 2.5x1.65 smd: 9(0.975,1.5)
SOP50P310X90-8N
  oval 0.3x0.851 smd: 1(0,0) 2(0.5,0) 3(1,0) 4(1.5,0) 5(1.5,3.1) 6(1,3.1) 7(0.5,3.1) 8(0,3.1)
SOP65P400X130-8A2N
  custom 0.1x0.1 smd: 1(0,0) 2(0.65,0) 3(1.3,0) 4(1.95,0) 5(1.95,3.54) 6(1.3,3.54) 7(0.65,3.54) 8(0,3.54)
SOP65P490X110-8A2N
  custom 0.113x0.113 smd: 1(0,0) 2(0.65,0) 3(1.3,0) 4(1.95,0) 5(1.95,4.3) 6(1.3,4.3) 7(0.65,4.3) 8(0,4.3)
SOT65P210X110-5N
  oval 0.399x0.899 smd: 1(0,0) 2(0.65,0) 3(1.3,0) 4(1.3,2.2) 5(0,2.2)
SOT95P280X145-5A2N
  custom 0.15x0.15 smd: 1(0,0) 2(0.95,0) 3(1.9,0) 4(1.9,2.29) 5(0,2.29)
SW_1188E1K2V_A2N
  round 0.099 hole 0.899 unplated: (2.229,0.6) (4.529,0.6)
  custom 0.25x0.25 smd: 1(0,0) 2(6.75,0)
  custom 0.225x0.225 smd: 3(1.275,1.8) 4(5.475,1.8)
TAGCONNECT_TC2050IDCNL_A2N
  round 0.1 hole 1 unplated: (-1.27,0.635) (6.35,-0.38) (6.35,1.65)
  round 0.8 smd: 1(0,0) 2(1.27,0) 3(2.54,0) 4(3.81,0) 5(5.08,0) 6(5.08,1.27) 7(3.81,1.27) 8(2.54,1.27) 9(1.27,1.27) 10(0,1.27)

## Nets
5V0: C10.1 C48.1 C110.1 C111.1 C151.1 C152.1 C157.1 C160.1 C161.1 C164.1 C168.1 C484.1 FL2.1 FL5.2 P10.3 R92.2 R354.2 U7.1 U7.2 U7.8 U42.1 U42.2 U42.8 U43.1 U43.3 U44.1 U44.3 U50.7(VCCB)
GND: C1.2 C2.2 C3.2 C4.2 C6.2 C7.2 C8.2 C9.2 C10.2 C11.2 C38.2 C39.2 C40.2 C42.2 C43.2 C44.2 C45.2 C46.2 C48.2 C49.2 C50.2 C70.2 C71.2 C72.2 C73.2 C74.2 C75.2 C78.2 C79.2 C80.2 C83.2 C84.2 C85.2 C86.2 C87.2 C88.1 C89.2 C108.2 C109.2 C110.2 C111.2 C113.2 C114.2 C115.2 C116.2 C117.2 C118.2 C119.2 C120.2 C121.2 C122.2 C124.1 C125.1 C126.1 C127.2 C128.2 C133.2 C134.2 C136.2 C137.2 C138.2 C139.2 C140.2 C141.2 C142.2 C143.2 C144.2 C145.2 C147.2 C149.2 C151.2 C152.2 C154.2 C155.2 C156.2 C157.2 C158.2 C159.2 C160.2 C161.2 C162.2 C163.2 C164.2 C165.2 C166.2 C168.2 C171.2 C174.2 C175.2 C484.2 C485.2 C486.2 C487.2 C488.2 CR4.1(C) CR5.1(C) CR6.3 CR7.4 CR15.2 CR16.4 J1.C1 J1.C2 J1.C15 J1.C16 J1.M1 J1.M2 J1.M3 J1.M4 MH1.1 MH2.1 MH3.1 MH4.1 MH5.1 P7.3 P7.5 P7.9 P8.3 P8.5 P8.9 P10.1 P10.2 P10.8 P10.14 P10.20 R10.1 R11.1 R28.1 R29.2 R30.2 R34.1 R62.1 R63.1 R65.1 R84.1 R90.1 R91.1 R93.2 R97.2 R105.1 R116.1 R117.1 R118.1 R122.1 R123.1 R125.1 R126.2 R127.2 R128.2 R129.2 R130.2 R133.1 R135.1 R136.1 R152.1 R353.1 R357.1 R358.1 R359.1 R364.2 SW3.1 SW3.2 SW3.4 U5.10 U5.17 U5.48 U5.55 U5.58 U5.64 U5.66 U5.80 U5.114 U6.1 U7.6 U7.9 U8.1 U8.5 U8.10 U8.11 U8.16 U9.1 U9.5 U9.10 U9.11 U9.13 U9.16 U10.9 U10.10 U10.11 U10.12 U10.16 U15.1 U15.2 U15.33 U33.6 U33.11 U34.4 U35.5 U35.10 U35.13 U35.14 U35.18 U35.26 U35.30 U35.31 U36.4(V-) U37.5(VS-) U38.6 U38.7 U38.8 U38.9 U38.10 U38.11 U39.7 U39.10 U39.11 U39.12 U40.7 U40.8 U41.2(V-) U42.6 U42.9 U43.2 U44.2 U46.6 U46.9 U47.8 U47.9 U49.1 U49.10 U49.11 U49.16 U50.2 Y3.2 Y3.4 Y4.2 Y4.4 Y5.2
VBUS_DET: R92.1 R93.1 U5.12
VDDC: C43.1 C44.1 C45.1 U5.87(VDDC#87) U5.115
ET_1V8: C128.1 C158.1 C159.1 U35.1 U43.5(OUT)
ET_3V3: C126.2 C141.1 C142.1 C153.1 C154.1 C155.1 C156.1 L333.1 L334.2 R132.2 U37.3 U37.10 U40.1(VIN) U40.2 U41.5 U42.3 U42.4(OUT#4)
ET_5V0: C125.2 C165.1 FL4.1 U36.7
ET_AVDD: C119.1 C120.1 C121.1 C122.1 L334.1 R98.1 U35.6 U35.32
ET_BYPASS: U5.78 U33.4 U33.8
ET_CAL0: R129.1 U5.74 U39.13
ET_CAL1: R128.1 U5.73 U39.5
ET_CAL2: R127.1 U5.23 U39.6
ET_CALIBRATE: U5.77 U38.4
ET_DVDD: C116.1 C117.1 L332.1 L333.2 R96.1 R114.1 R119.1 U35.27 Y5.1
ET_PM2: R96.2 U5.76 U35.17(START)
ET_PN3: R114.2 U5.110 U35.28
ET_SSICLK: U5.120 U35.22
ET_SSIDAT0: U5.123 U35.21
ET_SSIDAT1: U5.124 U35.20
ET_SSIFSS: U5.121 U35.19
ET_VDD: C172.1 C174.1 C485.1 C486.1 P9.1 R151.2 U46.3 U46.4(OUT#4)
ET_VREF: C127.1 C146.1 R121.1 U35.9 U40.5 U40.6
IRSTN: P8.10 R20.2
ITCK: P8.4 U5.100
ITDI: P8.8 U5.98
ITDO: P8.6 U5.97
ITMS: P8.2 U5.99
LP_VDD: P7.1 P9.3 P10.5 U38.5
LS_VDD: C70.1 C72.1 C74.1 C488.1 CR7.8(VCC) CR16.8(VCC) P9.2 R61.2 U8.2(VCCB) U9.2(VCCB) U10.2(VCCB) U33.3 U33.9 U49.2(VCCB)
SW_VDD: C114.1 C139.1 C140.1 C162.1 C163.1 R134.2 U33.1(VCC) U38.1(VCC) U39.14(VCC) U44.5(OUT)
USB1V8: C83.1 C84.1 C85.1 U15.15 U15.26
USB_VBUS: CR6.6 J1.C3 J1.C4(VBUS#C4) J1.C13 J1.C14 R82.2 U47.2 U47.3 U47.4
USBA1V8: C86.1 C87.1 U15.29
USBCLK: U5.92 U15.14
USBD0: U5.81 U15.24
USBD1: U5.82 U15.23
USBD2: U5.83 U15.22
USBD3: U5.84 U15.21
USBD4: U5.85 U15.20
USBD5: U5.86 U15.19
USBD6: U5.106 U15.18
USBD7: U5.105 U15.17
USBDIR: U5.104 U15.12
USBDM: CR6.4 J1.C7 J1.C10 U15.8
USBDP: CR6.5 J1.C6 J1.C11 U15.7
USBNXT: U5.103 U15.11
USBSTP: U5.91 U15.13
VCM: R100.1 R109.2 R111.2 R131.1 U41.1
XDS_BID_SCL: U5.112 U50.5
XDS_BID_SCL_LS: P10.6 U50.8
XDS_BID_SDA: U5.111 U50.4
XDS_BID_SDA_LS: P10.4 U50.1
XDS_DIR_GPIO1: U5.116 U49.4
XDS_DIR_GPIO2: U5.117 U49.5
XDS_DIR_TDI: U5.45
XDS_DIR_TDO: U5.46
XDS_GPIO1: U5.43 U49.7
XDS_GPIO1_LS: CR16.1 P10.18 R11.2 R12.1
XDS_GPIO2: U5.44 U49.8
XDS_GPIO2_LS: CR16.2 P10.16 R10.2 R13.1
XDS_GPIO3: R360.2 U5.42 U8.7
XDS_GPIO3_LS: CR16.3 P10.12 R15.1
XDS_NCS: R360.1 U5.6
XDS_PICO: R361.1 U5.11
XDS_POCI: R362.1 U5.27
XDS_RESET: R58.1 R363.1 U5.40 U10.1
XDS_RESET_LS: CR7.2 P7.10 P10.11 R57.1 U10.15
XDS_RX: U5.33 U8.8
XDS_RX_LS: CR16.6 P10.9 R61.1 R359.2 U8.13
XDS_SCLK: R365.1 U5.5
XDS_SWO: U5.25 U8.9
XDS_SWO_LS: CR16.7 P10.10 R62.2 U8.12
XDS_TCK: R365.2 U5.35 U9.6
XDS_TCK_LS: CR7.6 P7.4 P10.15 R16.1
XDS_TDI: R361.2 U5.38 U9.7
XDS_TDI_LS: CR7.3 P7.8 P10.19 R9.1
XDS_TDO: R362.2 U5.37 U9.9
XDS_TDO_LS: CR7.5 P7.6 P10.17 R63.2 U9.12
XDS_TMS: U5.36 U10.8
XDS_TMS_DIR: U5.24 U10.5
XDS_TMS_LS: CR7.7 P7.2 P10.13 R8.1 R65.2
XDS_TX: U5.34 U8.6
XDS_TX_LS: CR16.5 P10.7 R14.1
XDS_VDD: C2.1 C3.1 C4.1 C6.1 C7.1 C11.1 C38.1 C39.1 C40.1 C42.1 C47.1 C49.1 C71.1 C73.1 C75.1 C78.1 C79.1 C80.1 C113.1 C487.1 P8.1 R17.2 R18.2 R27.1 R31.2 R33.2 R39.1 R58.2 R83.1 U5.7 U5.8 U5.16 U5.26 U5.28 U5.39 U5.47 U5.51 U5.52 U5.69 U5.79 U5.90 U5.101 U5.113 U5.122 U7.3 U7.4(OUT#4) U8.3 U8.4 U9.3 U9.4 U10.3 U10.4 U15.6 U15.16 U15.25 U15.30 U15.31 U49.3 U50.3 U50.6
N2777344: R57.2 SW3.3
N2941019: R90.2 U5.95
N2941087: R91.2 U5.96
N2941323: R25.2 U5.4
N2941987: C89.1 R87.2 U15.28 Y4.1
N2942075: C88.2 R87.1 U15.27(XO) Y4.3
N2942253: R83.2 U15.5
N2942419: R39.2 U5.63
N2942527: R84.2 U15.32
N2942551: R27.2 U5.62
N2942639: R29.1 U5.61
N2942779: R30.1 U5.60
N2943199: C46.1 R31.1 U5.68
N2943999: R17.1 R20.1 U5.70
N2944041: C8.1 C50.1 R18.1 U5.9 U6.3
N2944467: C47.2 R33.1 R34.2 U7.5
N2944509: C9.1 U5.88 Y3.1
N2944561: C1.1 U5.89 Y3.3
N2944733: R28.2 U5.59
N2986125: C115.1 C118.1 L332.2 U34.6 U34.7 U34.8(VCC) Y5.4(VCC)
N2986433: R99.2 R107.2 U33.2
N2986453: U34.1 Y5.3
N2986493: U34.2 U34.3
N2986501: R94.2 U34.5
N2986505: R94.1 U35.24
N2986529: R107.1 R108.2 U33.7 U38.3
N2986711: C129.1 R95.2 R101.1 R102.2
N2986719: R95.1 R103.1 R104.2
N2986959: C123.1 C130.1 R102.1 U37.4
N2986967: C123.2 R103.2 U37.1
N2987171: R97.1 U35.29
N2987283: C124.2 C132.1 R99.1 U36.3
N2987343: R98.2 U35.8
N2987399: R137.2 U36.1
N2987403: R137.1 U36.8
N2987531: R101.2 U36.6
N2987583: C131.1 R104.1 U35.3
N2987595: R105.2 U35.23
N2987655: C132.2 C134.1 R108.1 U36.2
N2987667: C133.1 R111.1 U37.7
N2987683: C131.2 R113.1 U35.4
N2987711: R100.2 U36.5
N2987751: C130.2 C135.1 R110.1 U37.6
N2987759: C135.2 R112.2 U37.9
N2987811: C136.1 U35.2
N2987883: C129.2 R109.1 R110.2 R120.2
N2987963: C137.1 U35.11
N2988091: R112.1 R113.2 R120.1
N2988111: C138.1 U35.25
N2988211: R116.2 U35.7
N2988383: R117.2 U35.16
N2988415: R118.2 U35.15
N2988503: R119.2 U35.12
N2988673: U38.2 U39.2 U39.4 U39.9
N2989115: C143.1 R123.2 U39.1
N2989191: R136.2 U40.3
N2989203: C147.1 R121.2 R126.1 U41.3
N2989279: C145.1 U40.4
N2989287: C146.2 R122.2
N2989331: C144.1 R125.2 U39.3
N2989451: R131.2 U41.4
N2989545: C149.1 R130.1 U39.8
N2992079: C171.1 C175.1 FL5.1 U46.1 U46.2 U46.8
N2992279: C153.2 R132.1 R133.2 U42.5
N2992427: C172.2 R151.1 R152.2 U46.5
N2992751: C166.1 FL4.2 R354.1
N2993203: R134.1 R135.2 U44.4
N3010981: C109.1 CR15.1(CATHODE) FL2.2 U47.5(OUT)
N3012487: C108.1 U47.1
N3014332: R353.2 U47.7
N3192940: R23.2 U5.3
N3267387: R14.2 U8.15
N3267505: R9.2 U9.14
N3267702: R8.2 U10.13
N3268107: R12.2 U49.14
N3268153: R13.2 U49.13
N3268969: R15.2 U8.14
N3400495: J1.C5 R357.2
N3400502: J1.C12 R358.2
N3455582: R363.2 R364.1 U10.6
N3465637: R16.2 U9.15
N29414070: CR5.2 R25.1
N29414230: CR4.2 R23.1
N294220919: R82.1 U15.4

Pads without a net: CR6 1 2; CR7 1; FIDU1 1; FIDU2 1; FIDU3 1; FIDU4 1; FIDU5 1; FIDU6 1; J1 C8 C9; P7 7; P8 7; U5 1 2 13 14 15 18 19 20 21 22 29 30 31 32 41 49 50 53 54 56 57 65 67 71 72 75 93 94 102 107 108 109 118 119 125 126 127 128; U6 2 4 5; U7 7; U9 8; U10 7 14; U15 3 9 10; U33 5 10; U37 2 8; U42 7; U43 4; U46 7; U47 6; U49 6 9 12 15

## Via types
v1: diameter 0.4, hole 0.2, TOP to BOTTOM, 701 vias

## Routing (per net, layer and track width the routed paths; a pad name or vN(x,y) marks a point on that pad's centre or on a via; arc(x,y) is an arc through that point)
5V0: length 27.2
  TOP w0.15: C161.1 26.79,29.26 C160.1 ; U7.8 v1(26.98,38.97) ; U44.3 v1(24.02,29) ; U42.8 v1(31.35,42.72)
  TOP w0.3: 13.65,14.87 13.65,13.89 12.61,12.85 8.16,12.85 5.87,15.15 C10.1 3.96,15.15 3.79,14.98 3.36,14.98 2.98,15.36 U50.7 ; U43.3 v1(33.19,31.12)
  TOP w0.4: R92.2 v1(13.66,14.87)
  L3 w0.15: 26.31,25.66 26.3,25.67
  BOTTOM w0.15: 19.28,10.06 P10.3 ; P10.3 21.44,10.06 ; P10.3 20.36,11.14 ; P10.3 20.36,8.98
  BOTTOM w0.3: 13.7,14.87 v1(13.66,14.87)
  vias: v1(24.55,33.72) v1(24.55,33.22) v1(24.82,43.67) v1(24.82,43.11) v1(25.38,43.67) v1(25.38,43.11) v1(26.77,28.6) v1(26.77,28.1) v1(26.77,27.6) v1(29.15,38.47) v1(29.75,38.47) v1(30.32,21.62) v1(30.32,21) v1(33.19,34.18) v1(33.19,33.56) v1(33.15,32.94)
GND: length 223.1
  TOP w0.15: MH3.1 5.2,47.62 ; MH3.1 3.05,45.47 ; MH3.1 3.05,49.77 ; MH3.1 0.9,47.62 ; 33.06,11.52 P10.14 33.06,13.68 ; J1.M3 7.13,49.87 ; J1.M3 7.13,47.27 ; J1.M3 6.28,48.57 ; J1.M3 7.98,48.57 ; P10.20 40.68,13.68 ; P10.20 39.6,12.6 ; P10.20 41.76,12.6 ; 55.45,0.97 MH2.1 ; MH2.1 53.29,3.12 ; MH2.1 55.45,5.27 ; MH2.1 57.6,3.12 ; 55.45,45.47 MH4.1 ; MH4.1 57.6,47.62 ; MH4.1 53.3,47.62 ; MH4.1 55.45,49.77 ; J1.M4 7.13,45.32 ; J1.M4 7.13,42.82 ; J1.M4 6.28,44.07 ; J1.M4 7.98,44.07 ; 25.44,11.52 P10.8 ; P10.8 24.36,12.6 ; P10.8 26.52,12.6 ; P10.8 25.44,13.68 ; P10.1 17.82,11.14 ; P10.1 16.74,10.06 ; P10.1 17.82,8.98 ; P10.1 18.9,10.06 ; v1(16.95,16.68) 16.95,16.82 16.98,16.85 C2.2 ; J1.M2 15.77,49.87 ; J1.M2 14.92,48.57 ; J1.M2 16.62,48.57 ; J1.M2 15.77,47.27 ; 0.9,3.12 MH1.1 ; MH1.1 3.05,5.27 ; MH1.1 3.05,0.97 ; MH1.1 5.2,3.12 ; 2.08,8.23 MH5.1 ; MH5.1 3.19,9.33 ; MH5.1 3.19,7.13 ; MH5.1 4.29,8.23 ; 15.77,42.82 J1.M1 ; J1.M1 16.62,44.07 ; J1.M1 14.92,44.07 ; J1.M1 15.77,45.32 ; 16.74,12.6 P10.2 ; P10.2 17.82,13.68 ; P10.2 17.82,11.52
  L2 w0.15: 17.82,8.98 P10.1 ; P10.1 17.82,11.14 ; P10.1 16.74,10.06 ; P10.1 18.9,10.06 ; 55.45,0.97 MH2.1 ; MH2.1 57.6,3.12 ; MH2.1 53.29,3.12 ; MH2.1 55.45,5.27 ; MH5.1 3.19,9.33 ; MH5.1 2.08,8.23 ; MH5.1 3.19,7.13 ; MH5.1 4.29,8.23 ; J1.M4 7.13,45.32 ; J1.M4 7.13,42.82 ; J1.M4 6.28,44.07 ; J1.M4 7.98,44.07 ; J1.M3 7.98,48.57 ; J1.M3 7.13,47.27 ; J1.M3 6.28,48.57 ; J1.M3 7.13,49.87 ; 16.74,12.6 P10.2 ; P10.2 17.82,11.52 ; P10.2 17.82,13.68 ; P10.2 18.9,12.6 ; P10.8 26.52,12.6 ; P10.8 25.44,11.52 ; P10.8 25.44,13.68 ; P10.8 24.36,12.6 ; 0.9,3.12 MH1.1 ; MH1.1 3.05,0.97 ; MH1.1 5.2,3.12 ; MH1.1 3.05,5.27 ; 40.68,11.52 P10.20 ; P10.20 41.76,12.6 ; P10.20 40.68,13.68 ; P10.20 39.6,12.6 ; P10.14 34.14,12.6 ; P10.14 33.06,11.52 ; P10.14 33.06,13.68 ; P10.14 31.98,12.6 ; J1.M2 15.77,49.87 ; J1.M2 14.92,48.57 ; J1.M2 16.62,48.57 ; J1.M2 15.77,47.27 ; J1.M1 16.62,44.07 ; J1.M1 15.77,45.32 ; J1.M1 15.77,42.82 ; J1.M1 14.92,44.07 ; 55.45,45.47 MH4.1 ; MH4.1 55.45,49.77 ; MH4.1 53.3,47.62 ; MH4.1 57.6,47.62 ; MH3.1 3.05,49.77 ; MH3.1 0.9,47.62 ; MH3.1 5.2,47.62 ; MH3.1 3.05,45.47
  BOTTOM w0.15: P10.8 26.52,12.6 ; P10.8 25.44,13.68 ; P10.8 24.36,12.6 ; P10.8 25.44,11.52 ; MH3.1 3.05,49.77 ; MH3.1 3.05,45.47 ; MH3.1 5.2,47.62 ; MH3.1 0.9,47.62 ; 3.19,7.13 MH5.1 ; MH5.1 2.08,8.23 ; MH5.1 3.19,9.33 ; MH5.1 4.29,8.23 ; J1.M4 7.98,44.07 ; J1.M4 6.28,44.07 ; J1.M4 7.13,42.82 ; J1.M4 7.13,45.32 ; J1.M1 15.77,45.32 ; J1.M1 15.77,42.82 ; J1.M1 16.62,44.07 ; J1.M1 14.92,44.07 ; MH2.1 57.6,3.12 ; MH2.1 55.45,0.97 ; MH2.1 55.45,5.27 ; MH4.1 55.45,49.77 ; MH4.1 57.6,47.62 ; MH4.1 53.3,47.62 ; MH4.1 55.45,45.47 ; 17.82,8.98 P10.1 ; P10.1 17.82,11.14 ; P10.1 16.74,10.06 ; 16.74,12.6 P10.2 ; P10.2 17.82,11.52 ; P10.2 18.9,12.6 ; P10.2 17.82,13.68 ; 14.92,48.57 J1.M2 ; J1.M2 15.77,47.27 ; J1.M2 16.62,48.57 ; J1.M2 15.77,49.87 ; MH1.1 3.05,5.27 ; MH1.1 3.05,0.97 ; MH1.1 0.9,3.12 ; MH1.1 5.2,3.12 ; P10.14 33.06,13.68 ; P10.14 33.06,11.52 ; P10.14 31.98,12.6 ; P8.3 2.69,40.25 2.69,40.26 ; 39.82,11.74 P10.20 40.68,11.52 ; J1.M3 7.98,48.57 ; J1.M3 7.13,47.27 ; J1.M3 6.28,48.57 ; J1.M3 7.13,49.87
  BOTTOM w0.3: 45.02,26.81 45.02,26.81
  vias: v1(0.74,24.38) v1(0.7,23.83) v1(0.9,18.17) v1(0.83,14.97) v1(0.83,12.73) v1(0.95,45.4) v1(0.95,21.82) v1(1.07,4.79) v1(1.19,42.24) v1(1.14,41.12) v1(1.19,25.27) v1(1.45,17.87) v1(1.67,27.37) v1(1.65,25.77) v1(1.72,30.17) v1(2.05,34.77) v1(2.2,27.88) v1(2.19,11.74) v1(2.2,29.67) v1(2.24,28.91) v1(2.25,21.82) v1(2.69,38.95) v1(2.95,34.77) v1(3,14.06) v1(3.93,37.59) v1(4.24,36.23) v1(4.24,34.55) v1(4.36,36.78) v1(4.43,41.68) v1(4.63,18.65) v1(4.86,14.61) v1(4.97,38.65) v1(4.98,38.02) v1(4.94,1.07) v1(5.46,12.46) v1(5.58,49.18) v1(5.54,44.6) v1(5.61,3.85) v1(5.91,47.03) v1(6.11,40.44) v1(6.48,31.06) v1(7,6.09) v1(7.03,42.3) v1(7.19,9.67) v1(7.51,15.45) v1(7.71,22.65) v1(8.25,39.94) v1(8.27,37.7) v1(8.34,15.36) v1(8.79,12.16) v1(8.79,1.25) v1(8.85,19.7) v1(9.47,49.29) v1(9.43,47.2) v1(9.42,38.76) v1(9.45,28.54) v1(9.51,31.58) v1(10.58,39.97) v1(10.5,37.66) v1(10.56,25.69) v1(11.16,17.41) v1(11.1,13.55) v1(11.21,16.46) v1(11.49,41.77) v1(11.44,10.58) v1(11.69,35.14) v1(11.64,33) v1(11.65,19.87) v1(11.8,1.07) v1(12.04,23.1) v1(12.02,17.67) v1(12.07,5.02) v1(12.12,41.77) v1(12.3,42.83) v1(12.65,9.82) v1(12.7,14.12) v1(12.87,12.19) v1(13.12,49.3) v1(13.14,47.21) v1(13.17,39.88) v1(13.25,41.82) v1(13.66,35.11) v1(13.79,41.37) v1(13.79,40.75) v1(13.79,36.23) v1(13.85,37.47) v1(14.22,4.93) v1(14.35,35.85) v1(14.35,1.07) v1(14.9,39.33) v1(15.15,36.64) v1(15.65,25.75) v1(15.82,46.32) v1(15.9,39.08) v1(16.6,42.23) v1(16.59,40.09) v1(16.58,38.02) v1(16.55,32.97) v1(16.64,36.64) v1(16.64,1.25) v1(17.25,32.97) v1(17.24,13.78) v1(17.38,35.15) v1(17.4,21.83) v1(17.49,4.48) v1(17.5,20.5) v1(17.6,47.18) v1(17.65,44.68) v1(17.63,42.3) v1(17.76,28.48) v1(17.83,49.39) v1(18.05,30.22) v1(18.06,26.18) v1(18.54,42.88) v1(18.56,36.29) v1(18.59,8.73) v1(18.65,33.02) v1(18.69,13.53) v1(18.75,11.43) v1(18.81,38.77) v1(19.2,1.11) v1(19.74,37.59) v1(19.95,33.27) v1(19.96,4.3) v1(20.07,26.44) v1(20.25,29.82) v1(20.23,28.97) v1(20.32,5.38) v1(20.67,49.4) v1(20.68,47.27) v1(20.73,38.22) v1(20.75,25.96) v1(20.86,44.98) v1(20.86,38.89) v1(21.01,19.27) v1(21.17,35.67) v1(21.35,16.32) v1(21.31,13.6) v1(21.54,12.11) v1(21.6,40.44) v1(21.66,39.64) v1(21.65,25.96) v1(21.77,34.98) v1(21.85,1.07) v1(21.97,16.32) v1(22.28,28.41) v1(22.23,26.47) v1(22.41,30.67) v1(22.41,29.75) v1(22.5,49.45) v1(22.68,17.5) v1(22.64,13.97) v1(22.78,44.76) v1(22.88,28.38) v1(22.95,29) v1(23.15,1.34) v1(23.58,47.7) v1(23.52,13.97) v1(23.77,19.11) v1(23.96,45.65) v1(24.02,46.77) v1(24.06,38.92) v1(24.01,37) v1(24.23,16.4) v1(24.33,41.81) v1(24.52,37.92) v1(24.51,29.52) v1(24.76,44.97) v1(24.76,40.19) v1(24.76,39.51) v1(24.71,7.72) v1(24.97,29) v1(24.94,27.08) v1(25.03,38.94) v1(25.05,37.03) v1(25.2,31.88) v1(25.19,23.95) v1(25.13,21.78) v1(25.69,46.83) v1(25.73,32.42) v1(25.72,30.11) v1(26.06,21.1) v1(26.25,13.53) v1(26.29,1.07) v1(26.4,26.99) v1(26.42,16.63) v1(26.51,5.02) v1(26.87,24.01) v1(26.93,21.72) v1(27.12,38.46) v1(27.35,16.31) v1(27.54,18.87) v1(27.67,28.6) v1(27.65,27.65) v1(27.72,37.91) v1(27.74,29.89) v1(28.19,28.7) v1(28.3,18.91) v1(28.47,13.96) v1(28.98,18.91) v1(29.15,40.67) v1(29.21,9.26) v1(29.38,13.95) v1(29.43,1.29) v1(29.63,4.24) v1(30.15,40.58) v1(30.1,31.22) v1(30.1,29.42) v1(30.16,28.21) v1(30.2,41.67) v1(30.2,25.67) v1(30.34,47.76) v1(30.49,31.93) v1(30.6,13.97) v1(30.61,32.44) v1(30.6,30.32) v1(30.75,40.02) v1(30.86,6.32) v1(31.1,31.22) v1(31.1,29.42) v1(31.3,49.49) v1(31.45,40.87) v1(31.45,40.12) v1(31.45,33.67) v1(31.45,33.12) v1(31.45,32.47) v1(31.41,27.04) v1(31.64,24.2) v1(31.8,25.17) v1(31.85,43.07) v1(31.81,1.11) v1(32.02,15.46) v1(32.2,47.67) v1(32.35,43.55) v1(32.35,40.52) v1(32.33,37.16) v1(32.39,24.2) v1(32.33,18.62) v1(32.51,16.31) v1(32.65,25.4) v1(32.8,46.67) v1(32.8,44.92) v1(32.88,3.81) v1(32.95,36.47) v1(32.95,26.32) v1(33.07,40.88) v1(33.07,40.13) v1(33.07,24.14) v1(33.07,23.33) v1(33.06,16.31) v1(33.01,7.22) v1(33.15,32.07) v1(33.29,48.48) v1(33.45,49.07) v1(33.57,18.99) v1(33.57,17.32) v1(33.61,13.93) v1(34.12,18.87) v1(34.2,45.67) v1(34.27,13.97) v1(34.37,40.5) v1(34.35,29.87) v1(34.39,28.22) v1(34.55,43.67) v1(34.68,41.12) v1(34.65,35.57) v1(34.68,1.25) v1(34.92,26.28) v1(35.4,36.17) v1(35.36,23.26) v1(35.85,29.07) v1(35.85,28.37) v1(35.89,4.84) v1(35.95,43.17) v1(36.2,35.67) v1(36.3,34.7) v1(36.31,31.86) v1(36.82,34.17) v1(36.95,31.87) v1(37.49,26.78) v1(37.55,29.57) v1(37.59,1.34) v1(37.66,18.31) v1(38.04,4.52) v1(38.46,20.11) v1(38.75,31.91) v1(38.79,13.93) v1(38.98,6.36) v1(39.05,33.97) v1(39.25,43.37) v1(39.21,17.2) v1(39.38,38.23) v1(39.38,10.41) v1(39.48,9.15) v1(39.66,38.82) v1(39.65,33.97) v1(39.61,31.42) v1(39.6,25.47) v1(39.86,41.42) v1(39.83,13.95) v1(39.95,43.87) v1(40.08,20.11) v1(40.3,32.06) v1(40.35,25.47) v1(40.32,19.05) v1(40.4,35.38) v1(40.46,1.16) v1(40.65,43.87) v1(40.65,42.77) v1(40.7,19.48) v1(40.7,27.7) v1(40.73,5.15) v1(40.89,47.51) v1(40.85,25.47) v1(41.05,33.06) v1(41.26,27.12) v1(41.25,22.87) v1(41.35,36.87) v1(41.4,35.92) v1(41.36,16.56) v1(41.45,43.87) v1(41.53,45.67) v1(41.55,44.97) v1(41.85,33.06) v1(41.96,47.29) v1(42.05,45.67) v1(42.05,28.87) v1(42.01,10.68) v1(42.22,49.37) v1(42.28,34.06) v1(42.35,40.77) v1(42.35,38.78) v1(42.35,38.26) v1(42.35,37.73) v1(42.53,13.58) v1(42.75,48.57) v1(42.75,41.57) v1(42.75,25.67) v1(42.75,24.27) v1(42.89,13.16) v1(42.98,1.2) v1(43.15,18.77) v1(43.32,21) v1(43.65,45.47) v1(43.65,33.41) v1(43.78,9.32) v1(43.96,33.83) v1(43.95,29.88) v1(43.95,28.32) v1(43.95,23.82) v1(44.16,3.94) v1(44.25,45.07) v1(44.3,33.39) v1(44.43,47.67) v1(44.45,43.87) v1(44.45,18.77) v1(44.75,38.77) v1(44.7,37.37) v1(44.73,1.38) v1(44.99,48.18) v1(45.07,34.77) v1(45.15,43.87) v1(45.14,20.38) v1(45.22,6.23) v1(45.35,24.17) v1(45.54,47.67) v1(45.53,15.64) v1(45.75,41.57) v1(45.74,18.42) v1(45.85,28.87) v1(45.95,32.77) v1(46.18,26.2) v1(46.2,49.67) v1(46.2,45.67) v1(46.2,25.67) v1(46.34,19.75) v1(46.55,40.27) v1(46.55,39.77) v1(46.6,38.27) v1(46.67,26.82) v1(46.65,22.88) v1(46.79,9.32) v1(47.1,26.26) v1(47.3,48.52) v1(47.35,35.67) v1(47.45,24.13) v1(47.9,43.07) v1(47.95,12.91) v1(48,36.77) v1(48.2,35.67) v1(48.2,31.67) v1(48.35,22.89) v1(48.55,30.87) v1(48.55,29.37) v1(48.7,49.12) v1(48.75,23.77) v1(48.95,25.37) v1(48.94,15.64) v1(49.05,36.52) v1(49.21,0.8) v1(49.35,32.52) v1(49.52,38.26) v1(49.63,9.61) v1(49.75,17.72) v1(49.85,30.87) v1(49.85,29.37) v1(50.04,23.4) v1(50.12,43.67) v1(50.2,49.67) v1(50.28,48.32) v1(50.2,45.67) v1(50.2,25.67) v1(50.21,20.3) v1(50.35,34.17) v1(50.35,33.57) v1(50.35,32.97) v1(50.47,1.16) v1(50.55,35.87) v1(50.55,31.67) v1(50.55,30.77) v1(50.55,29.77) v1(50.55,26.77) v1(50.56,9.93) v1(50.69,41.57) v1(50.8,46.77) v1(50.7,42.32) v1(50.71,39.25) v1(50.96,45.92) v1(51.05,36.82) v1(51.15,28.17) v1(51.28,43.67) v1(51.36,17.13) v1(51.36,16.51) v1(51.77,26.33) v1(51.9,46.91) v1(52.45,27.17) v1(52.48,25.87) v1(52.67,4.14) v1(52.95,30.17) v1(52.97,14.71) v1(53.05,41.35) v1(53.65,37.07) v1(53.75,41.37) v1(53.75,33.87) v1(53.73,9.85) v1(53.72,6.9) v1(53.96,14.71) v1(54.2,45.67) v1(54.35,40.57) v1(54.35,39.87) v1(54.35,36.32) v1(54.4,8.26) v1(54.65,29.07) v1(54.95,21.62) v1(54.96,14.71) v1(55.24,40.8) v1(55.55,36.97) v1(55.7,29.59) v1(55.76,17.44) v1(55.82,16.26) v1(56.01,27.11) v1(56.01,25.75) v1(56.2,39.67) v1(56.4,41.48) v1(56.35,36.97) v1(56.4,42.17) v1(56.44,32.03) v1(56.88,17.85) v1(57.06,28.51) v1(57.15,29.07) v1(57.39,12.56) v1(57.32,7.75) v1(57.46,44.77) v1(57.46,40.52) v1(57.41,36.16) v1(57.48,33.24) v1(57.45,28.12) v1(57.45,20.87) v1(57.41,5.52) v1(57.54,14.53) v1(57.75,26.17)
VBUS_DET: length 7.2
  TOP w0.15: R93.1 R92.1 10.12,15.3 v1(9.65,15.77) ; U5.12 9.65,19.82 v1(9.74,19.9)
  BOTTOM w0.15: v1(9.65,15.77) 9.65,16.17 9.74,16.26 v1(9.74,19.9)
VDDC: length 15.6
  TOP w0.2: U5.87 8.85,27.82 6.42,25.39 U5.115 2.86,25.39 2.74,25.27 C43.1 C44.1 C45.1
ET_1V8: length 6.8
  TOP w0.3: U35.1 42.65,36.32 41.05,34.72 C128.1 41.05,34.56 39.65,33.16 C159.1 C158.1 37.54,32.97 U43.5
ET_3V3: length 6.9
  TOP w0.15: U37.3 42.51,29.72 v1(42.21,30.02) ; v1(36.25,39.17) 36.25,41.02 C153.1 35.18,42.05 R132.2
  TOP w0.3: U41.5 C141.1 v1(34.95,24.63)
  vias: v1(34.45,38.37) v1(36.23,38.64) v1(37.05,40.07) v1(37.58,40.07) v1(43.45,31.77) v1(44.45,31.77) v1(54.65,44.77) v1(55.25,44.77) v1(55.85,44.77)
ET_5V0: length 5
  TOP w0.15: 40.73,20.96 40.73,20.97
  TOP w0.3: U36.7 40.73,20.96 ; FL4.1 39.26,21.78 C165.1 40.05,21.77 40.7,21.12 40.7,20.99 ; 40.7,20.99 C125.2 ; 40.7,20.99 40.73,20.97
ET_AVDD: length 5.2
  TOP w0.3: C119.1 45.95,34.32 45.95,34.77 45.2,35.52 U35.6 ; R98.1 47.8,33.72 C122.1 ; U35.32 C120.1
  vias: v1(37.05,36.07) v1(37.65,36.07) v1(38.18,36.07) v1(38.6,37.42) v1(46.75,34.16) v1(46.75,33.63) v1(46.75,33.07)
ET_BYPASS: length 65.4
  TOP w0.15: U33.8 v1(54.25,28.69) ; v1(55.65,24.37) 55.62,24.39 55.03,24.39 54.75,24.68 U33.4 ; U5.78 v1(12.45,32.12)
  BOTTOM w0.15: v1(12.45,32.12) 13.14,31.43 16.63,31.43 16.95,31.75 21.4,31.75 22.5,32.85 24.03,32.85 24.08,32.8 24.73,32.8 25.77,33.84 29.42,33.84 31.62,36.04 33.12,36.04 34.07,37 36.46,37 37.56,38.09 37.56,38.1 39.85,40.39 40.4,40.39 42.4,42.39 46.51,42.39 49.95,38.95 49.95,38.95 50.37,38.53 50.5,38.53 54.92,34.1 54.92,30.12 54.22,29.42 54.22,28.71 v1(54.25,28.69) 55.58,27.35 55.58,24.84 55.65,24.77 v1(55.65,24.37)
ET_CAL0: length 58.8
  TOP w0.15: U39.13 56.2,30.37 R129.1 v1(57.15,30.07) ; v1(14.05,32.17) U5.74
  BOTTOM w0.15: v1(14.05,32.17) 16.52,32.17 16.7,32.35 19.24,32.35 19.3,32.4 21.07,32.4 22.31,33.64 23.44,33.64 24.25,34.44 29,34.44 32.15,37.6 36.21,37.6 36.96,38.34 36.96,38.35 39.6,40.99 40.15,40.99 42.15,42.99 46.76,42.99 49.83,39.92 50.65,39.92 51.36,39.21 51.36,38.52 55.52,34.35 55.52,34.22 57.45,32.3 57.45,30.38 v1(57.15,30.07)
ET_CAL1: length 54.8
  TOP w0.15: v1(15.8,30.17) 15.8,32.02 14.45,33.37 U5.73 ; U39.5 53.55,31.67 v1(52.85,31.67) R128.1
  BOTTOM w0.15: v1(52.85,31.67) 52.85,35.71 50.33,38.23 50.24,38.23 49.65,38.83 49.65,38.83 46.38,42.09 42.53,42.09 40.53,40.09 39.97,40.09 37.86,37.98 37.86,37.97 36.59,36.69 34.21,36.69 33.25,35.74 31.77,35.74 27.5,31.47 25.39,31.47 25.37,31.46 23.04,31.46 23.03,31.44 17.07,31.44 v1(15.8,30.17)
ET_CAL2: length 51.3
  TOP w0.15: U39.6 v1(52.83,30.77) R127.1 ; U5.23 v1(14.05,25.37)
  BOTTOM w0.15: 48.8,26.74 v1(52.83,30.77) ; v1(14.05,25.37) 15.43,25.37 15.57,25.22 23.93,25.22 24.97,26.27 27.44,26.27 28.65,27.48 33.01,27.48 33.75,26.75
  BOTTOM w0.2: 33.75,26.75 35.48,25.02 47.08,25.02 48.8,26.74
ET_CALIBRATE: length 71.5
  TOP w0.15: v1(12.88,32.62) 12.85,32.65 U5.77 ; v1(53.45,19.08) U38.4
  BOTTOM w0.15: v1(53.45,19.08) 53.89,18.64 55.08,18.64 56.2,19.76 56.2,25.33 56.44,25.57 56.44,27.29 56.12,27.6 56.12,31.47 56.02,31.58 56.02,32.21 56.12,32.32 56.12,33.2 55.22,34.1 55.22,34.23 50.63,38.83 50.5,38.83 46.63,42.69 42.28,42.69 40.28,40.69 39.72,40.69 37.26,38.23 37.26,38.22 36.34,37.3 33.17,37.3 32.22,36.34 31.47,36.34 29.27,34.14 24.37,34.14 23.57,33.34 22.44,33.34 21.14,32.05 16.82,32.05 16.52,31.75 13.75,31.75 v1(12.88,32.62)
ET_DVDD: length 21.6
  TOP w0.15: R119.1 v1(50.1,40.6) ; R96.1 v1(48.05,43.97)
  TOP w0.3: U35.27 C116.1 39.69,40.27 39,40.96 R114.1 39,42.22 38.05,43.17 37.55,43.17 L333.2
  BOTTOM w0.3: v1(50.1,40.6) 50.1,41.92 v1(48.05,43.97) 47.55,44.47 37.85,44.47 v1(37.75,44.37)
